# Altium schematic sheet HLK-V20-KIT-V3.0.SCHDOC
size A4
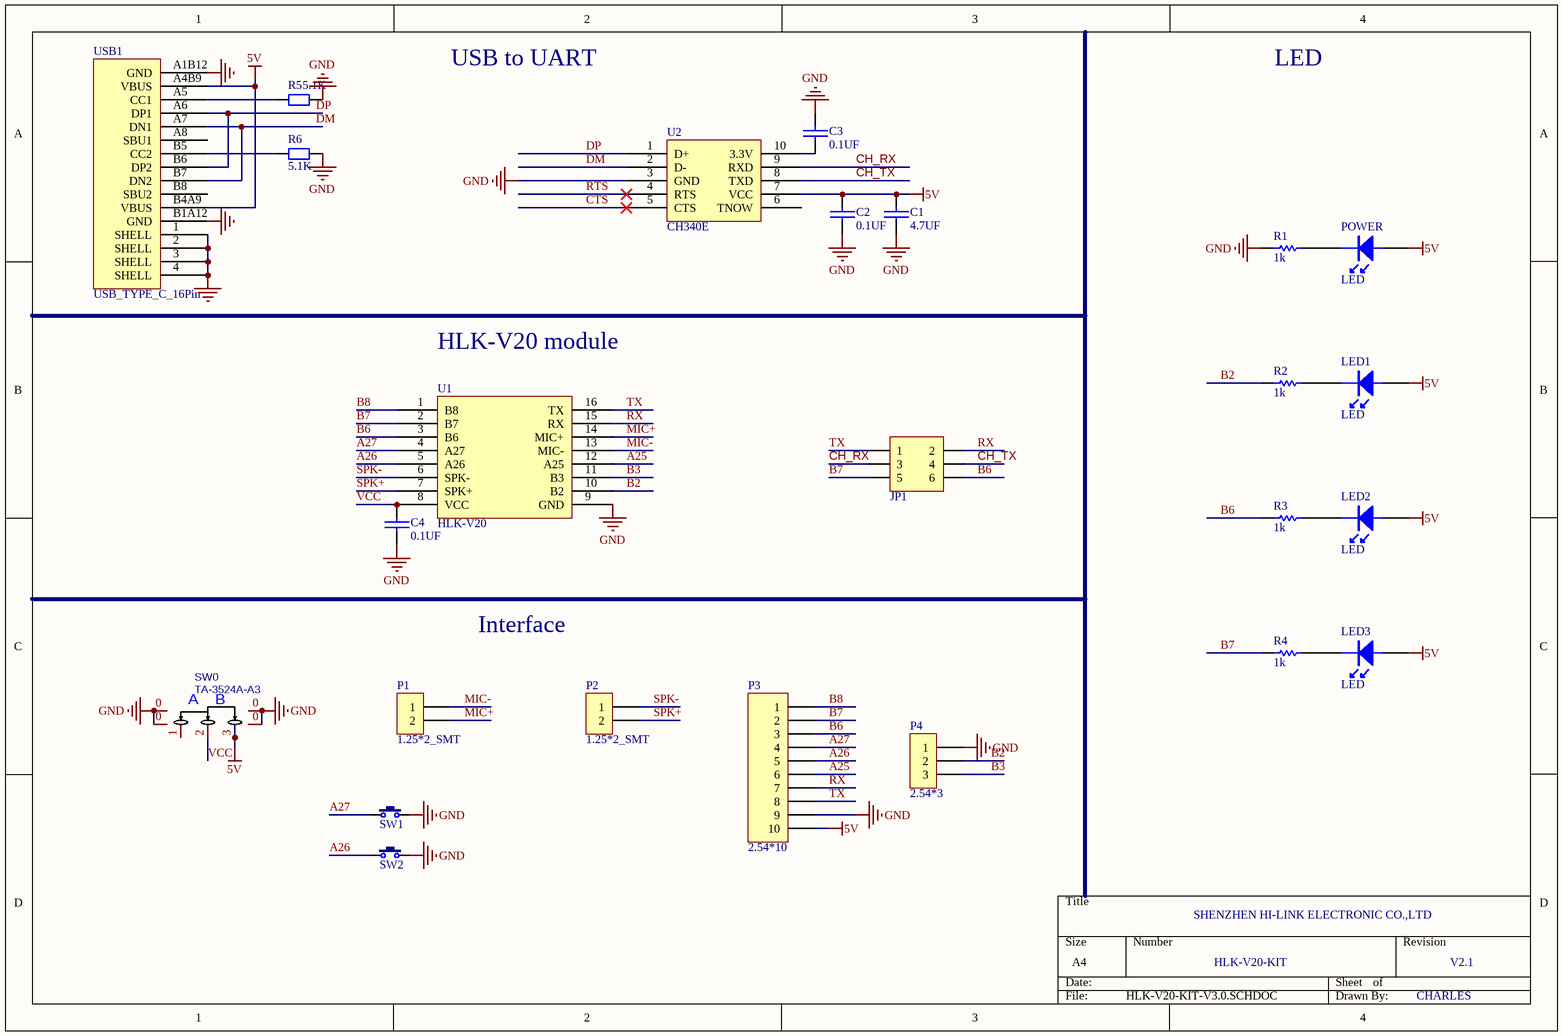
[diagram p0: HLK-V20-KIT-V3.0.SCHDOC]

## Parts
C1  4.7UF  [C 0603_L]
C2  0.1UF  [C 0603_L]
C3  0.1UF  [C 0603_L]
C4  0.1UF  [C 0603_L]
JP1  Header3X2  [HDR2.54-LI-2x3P]  (value not drawn)
LED1  LED  [LED 0603B-L]
LED2  LED  [LED 0603B-L]
LED3  LED  [LED 0603B-L]
P1  1.25*2_SMT  [MX 1.25-LS-2P]
P2  1.25*2_SMT  [PH2.0-LS-2P]
P3  2.54*10  [HDR1X10]
P4  2.54*3  [HDR2.54-LI-3P]
POWER  LED  [LED 0603B-L]
R1  value 1k  [R 0603_L]  (hidden comment: Res1)
R2  value 1k  [R 0603_L]  (hidden comment: Res1)
R3  value 1k  [R 0603_L]  (hidden comment: Res1)
R4  value 1k  [R 0603_L]  (hidden comment: Res1)
R5  5.1K  [R 0402_L]
R6  5.1K  [R 0402_L]
SW0  TA-3524A-A3  [SW-SMD_3P-L6.6-W2.7-P1.50]
SW1  3x6x5  [KEY-K2]  (value not drawn)
SW2  3x6x5  [KEY-K2]  (value not drawn)
U1  HLK-V20  [HLK-V20]
U2  CH340E  [MSOP-10]
USB1  USB_TYPE_C_16Pin  [USB-C-16PIN-1]

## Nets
5V: C1.2 C2.2 LED1.1 LED2.1 LED3.1 P3.10 POWER.1 SW0.3 U2.7(VCC) USB1.A4B9(VBUS) USB1.B4A9(VBUS)
GND: C1.1 C2.1 C3.1 C4.1 P3.9 P4.1 R1.2 R5.1 R6.1 SW0.0 SW1.2 SW2.2 U1.9(GND) U2.3(GND) USB1.1(SHELL) USB1.2(SHELL) USB1.3(SHELL) USB1.4(SHELL) USB1.A1B12(GND) USB1.B1A12(GND)
A25: P3.6 U1.12(A25)
A26: P3.5 SW2.1 U1.5(A26)
A27: P3.4 SW1.1 U1.4(A27)
B2: P4.2 R2.2 U1.10(B2)
B3: P4.3 U1.11(B3)
B6: JP1.6 P3.3 R3.2 U1.3(B6)
B7: JP1.5 P3.2 R4.2 U1.2(B7)
B8: P3.1 U1.1(B8)
CH_RX: JP1.3 U2.9(RXD)
CH_TX: JP1.4 U2.8(TXD)
CTS: U2.5(CTS)
DM: U2.2(D-) USB1.A7(DN1) USB1.B7(DN2)
DP: U2.1(D+) USB1.A6(DP1) USB1.B6(DP2)
MIC+: P1.2 U1.14(MIC+)
MIC-: P1.1 U1.13(MIC-)
RTS: U2.4(RTS)
RX: JP1.2 P3.7 U1.15(RX)
SPK+: P2.2 U1.7(SPK+)
SPK-: P2.1 U1.6(SPK-)
TX: JP1.1 P3.8 U1.16(TX)
VCC: C4.2 SW0.2 U1.8(VCC)
NetC3_2: C3.2 U2.10(3.3V)
NetLED1_2: LED1.2 R2.1
NetLED2_2: LED2.2 R3.1
NetLED3_2: LED3.2 R4.1
NetPOWER_2: POWER.2 R1.1
NetR5_2: R5.2 USB1.A5(CC1)
NetR6_2: R6.2 USB1.B5(CC2)

Not connected (* = marked no-connect by the designer): SW0 1; U2 6(TNOW); USB1 A8(SBU1) B8(SBU2)

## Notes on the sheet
- USB to UART
- LED
- HLK-V20 module
- Interface
- SHENZHEN HI-LINK ELECTRONIC CO.,LTD
- HLK-V20-KIT
- V2.1
- CHARLES

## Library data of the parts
C1-C4 = CAP: Capacitor
JP1 = Header 3X2: 3*2P接插件; 版权归属: 源创客
P1 P2 = CON2: Connector
P3 = Header 10: Header, 10-Pin
P4 = CON3: Connector
R1-R4 = Res1: Resistor
R5 R6 = R: 贴片电阻; 版权归属: 源创客
SW0 = TA-3524A-A3: BOM_Manufacturer: Yuandi; Contributor: LCSC
SW1 SW2 = TSW 3x6: 3x6轻触开关; 版权归属: 源创客
U1 = HLK-V20: HLK-V20语音模块
USB1 = USB_TYPE_C_16Pin: TYPE_C_16Pin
